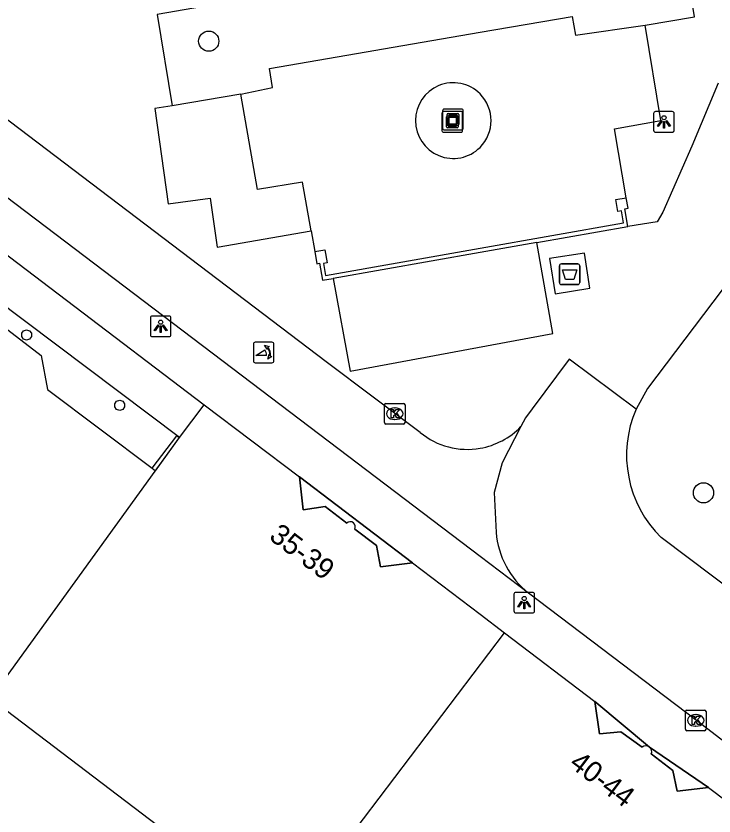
# Model space of a CAD drawing. Extents: x 161882 to 162509, y 381687 to 382379.
# Drawn here: x 161977.53 to 162011.33, y 382252.2 to 382290.93 of the extents above; entities that cross this region are included whole.
import ezdxf

# ---------------------------------------------------------------- set-up
doc = ezdxf.new("R2010")
doc.units = 0
for name, color, linetype in [('IMGEO_Afval_apart_plaats', 7, 'Continuous'), ('IMGEO_Boom', 7, 'Continuous'), ('IMGEO_Fietspad_open', 7, 'Continuous'), ('IMGEO_Kolk', 7, 'Continuous'), ('IMGEO_Kunstobject', 7, 'Continuous'), ('IMGEO_Lichtpunt', 7, 'Continuous'), ('IMGEO_Muur', 7, 'Continuous'), ('IMGEO_Pand', 7, 'Continuous'), ('IMGEO_Pand_nummerreeks', 7, 'Continuous'), ('IMGEO_Pand_overbouw', 7, 'Continuous'), ('IMGEO_Parkeervlak_open', 7, 'Continuous'), ('IMGEO_Poller', 7, 'Continuous'), ('IMGEO_Rijbaan_lokaal_open', 7, 'Continuous'), ('IMGEO_Voetpad_open', 7, 'Continuous')]:
    doc.layers.add(name, color=color, linetype=linetype)

msp = doc.modelspace()

# ---------------------------------------------------------------- linework, layer by layer
at = {"layer": 'IMGEO_Afval_apart_plaats'}
for p, q in [((162003.941, 382278.932), (162004.731, 382278.932)), ((162004.731, 382278.932), (162003.941, 382278.932)), ((162003.841, 382278.032), (162003.841, 382278.832)), ((162003.841, 382278.832), (162003.841, 382278.032)), ((162004.831, 382278.832), (162004.831, 382278.032)), ((162004.831, 382278.032), (162004.831, 382278.832)), ((162004.731, 382277.932), (162003.941, 382277.932)), ((162003.941, 382277.932), (162004.731, 382277.932))]:
    msp.add_line(p, q, dxfattribs=at)
msp.add_lwpolyline([(162003.984, 382278.646), (162004.688, 382278.646), (162004.539, 382278.176), (162004.133, 382278.176), (162003.984, 382278.646)], dxfattribs=at)
for centre, start, end in [((162003.941, 382278.832), 90, 180), ((162003.941, 382278.832), 90, 180), ((162004.731, 382278.832), 0, 90), ((162004.731, 382278.832), 360, 90), ((162003.941, 382278.032), 180, 270), ((162003.941, 382278.032), 180, 270), ((162004.731, 382278.032), 270, 0), ((162004.731, 382278.032), 270, 0)]:
    msp.add_arc(centre, 0.1, start, end, dxfattribs=at)
at = {"layer": 'IMGEO_Boom'}
for centre in [(161986.861, 382289.713), (162010.82, 382267.85)]:
    msp.add_circle(centre, 0.489, dxfattribs=at)
at = {"layer": 'IMGEO_Fietspad_open'}
msp.add_lwpolyline([(162002.346, 382262.989), (162000, 382264.77), (161990.844, 382271.72), (161969.897, 382287.586)], dxfattribs=at)
at = {"layer": 'IMGEO_Kolk'}
for p, q in [((161995.369, 382271.252), (161995.369, 382272.104)), ((161995.444, 382272.178), (161996.296, 382272.178)), ((161995.857, 382271.958), (161995.882, 382271.958)), ((161996.37, 382272.104), (161996.37, 382271.252)), ((161996.296, 382271.178), (161995.444, 382271.178)), ((161995.88, 382271.398), (161995.855, 382271.398)), ((162009.945, 382256.408), (162009.945, 382257.26)), ((162010.02, 382257.334), (162010.872, 382257.334)), ((162010.946, 382257.26), (162010.946, 382256.408)), ((162010.433, 382257.114), (162010.458, 382257.114)), ((162010.456, 382256.554), (162010.431, 382256.554)), ((162010.872, 382256.334), (162010.02, 382256.334))]:
    msp.add_line(p, q, dxfattribs=at)
for points in [[(161995.369, 382271.252), (161995.369, 382272.104)], [(161995.444, 382272.178), (161996.296, 382272.178)], [(161996.37, 382272.104), (161996.37, 382271.252)], [(161995.69, 382271.878), (161995.813, 382271.878), (161995.813, 382271.727), (161995.943, 382271.878), (161996.107, 382271.878), (161995.961, 382271.727), (161996.114, 382271.478), (161995.962, 382271.478), (161995.877, 382271.642), (161995.813, 382271.575), (161995.813, 382271.478), (161995.69, 382271.478), (161995.69, 382271.878)], [(161996.296, 382271.178), (161995.444, 382271.178)], [(162009.945, 382256.408), (162009.945, 382257.26)], [(162010.02, 382257.334), (162010.872, 382257.334)], [(162010.946, 382257.26), (162010.946, 382256.408)], [(162010.266, 382257.034), (162010.389, 382257.034), (162010.389, 382256.883), (162010.519, 382257.034), (162010.683, 382257.034), (162010.537, 382256.883), (162010.69, 382256.634), (162010.538, 382256.634), (162010.453, 382256.798), (162010.389, 382256.731), (162010.389, 382256.634), (162010.266, 382256.634), (162010.266, 382257.034)], [(162010.872, 382256.334), (162010.02, 382256.334)]]:
    msp.add_lwpolyline(points, dxfattribs=at)
for centre, start, end in [((161995.446, 382272.102), 91.552, 178.448), ((161995.446, 382272.102), 91.552, 178.448), ((161996.294, 382272.102), 1.552, 88.448), ((161996.294, 382272.102), 1.552, 88.448), ((161995.446, 382271.254), 181.552, 268.448), ((161995.446, 382271.254), 181.552, 268.448), ((161996.294, 382271.254), 271.552, 358.448), ((161996.294, 382271.254), 271.552, 358.448), ((162010.022, 382257.258), 91.552, 178.448), ((162010.022, 382257.258), 91.552, 178.448), ((162010.87, 382257.258), 1.552, 88.448), ((162010.87, 382257.258), 1.552, 88.448), ((162010.022, 382256.41), 181.552, 268.448), ((162010.022, 382256.41), 181.552, 268.448), ((162010.87, 382256.41), 271.552, 358.448), ((162010.87, 382256.41), 271.552, 358.448)]:
    msp.add_arc(centre, 0.0765, start, end, dxfattribs=at)
for centre, major_axis, ratio, start_param, end_param in [((161995.856, 382271.678), (-0.387, 0.002), 0.722429, 4.712389, 7.853982), ((161995.881, 382271.678), (-0.39, 0.002), 0.717154, 1.570796, 4.712389), ((162010.432, 382256.834), (-0.387, 0.002), 0.722429, 4.712389, 7.853982), ((162010.457, 382256.834), (-0.39, 0.002), 0.717154, 1.570796, 4.712389)]:
    msp.add_ellipse(centre, major_axis=major_axis, ratio=ratio, start_param=start_param, end_param=end_param, dxfattribs=at)
at = {"layer": 'IMGEO_Kunstobject'}
for p, q in [((161998.186, 382286.339), (161998.186, 382285.498)), ((161998.186, 382286.339), (161998.186, 382285.498)), ((161999.072, 382286.304), (161998.231, 382286.304)), ((161999.072, 382286.304), (161998.231, 382286.304)), ((161999.102, 382286.423), (161998.261, 382286.423)), ((161999.102, 382286.423), (161998.261, 382286.423)), ((161999.156, 382285.388), (161999.156, 382286.229)), ((161999.156, 382285.388), (161999.156, 382286.229)), ((161999.186, 382285.507), (161999.186, 382286.348)), ((161999.186, 382285.507), (161999.186, 382286.348)), ((161998.156, 382286.22), (161998.156, 382285.379)), ((161998.156, 382286.22), (161998.156, 382285.379)), ((161998.37, 382285.568), (161998.37, 382286.042)), ((161998.4, 382285.687), (161998.4, 382286.161)), ((161998.42, 382286.092), (161998.894, 382286.092)), ((161998.45, 382286.211), (161998.924, 382286.211)), ((161998.45, 382285.992), (161998.45, 382285.618)), ((161998.844, 382286.012), (161998.47, 382286.012)), ((161998.48, 382286.111), (161998.48, 382285.737)), ((161998.874, 382286.131), (161998.5, 382286.131)), ((161998.864, 382285.618), (161998.864, 382285.992)), ((161998.894, 382285.737), (161998.894, 382286.111)), ((161998.944, 382286.042), (161998.944, 382285.568)), ((161998.974, 382286.161), (161998.974, 382285.687)), ((161998.894, 382285.518), (161998.42, 382285.518)), ((161998.924, 382285.637), (161998.45, 382285.637)), ((161998.47, 382285.598), (161998.844, 382285.598)), ((161998.5, 382285.717), (161998.874, 382285.717)), ((161998.24, 382285.304), (161999.081, 382285.304)), ((161998.24, 382285.304), (161999.081, 382285.304)), ((161998.27, 382285.423), (161999.111, 382285.423)), ((161998.27, 382285.423), (161999.111, 382285.423))]:
    msp.add_line(p, q, dxfattribs=at)
for centre, radius, start, end in [((161998.234, 382286.226), 0.0779, 92.4484, 184.2845), ((161998.234, 382286.226), 0.0779, 92.4484, 184.2845), ((161998.264, 382286.345), 0.0779, 92.4484, 184.2845), ((161998.264, 382286.345), 0.0779, 92.4484, 184.2845), ((161999.078, 382286.226), 0.0779, 2.4484, 94.2845), ((161999.078, 382286.226), 0.0779, 2.4484, 94.2845), ((161999.108, 382286.345), 0.0779, 2.4484, 94.2845), ((161999.108, 382286.345), 0.0779, 2.4484, 94.2845), ((161998.42, 382286.042), 0.05, 90, 180), ((161998.45, 382286.161), 0.05, 90, 180), ((161998.47, 382285.992), 0.02, 90, 180), ((161998.5, 382286.111), 0.02, 90, 180), ((161998.844, 382285.992), 0.02, 360, 90), ((161998.874, 382286.111), 0.02, 360, 90), ((161998.894, 382286.042), 0.05, 360, 90), ((161998.924, 382286.161), 0.05, 360, 90), ((161998.264, 382285.501), 0.0779, 182.4484, 274.2845), ((161998.264, 382285.501), 0.0779, 182.4484, 274.2845), ((161998.42, 382285.568), 0.05, 180, 270), ((161998.45, 382285.687), 0.05, 180, 270), ((161998.47, 382285.618), 0.02, 180, 270), ((161998.5, 382285.737), 0.02, 180, 270), ((161998.844, 382285.618), 0.02, 270, 0), ((161998.874, 382285.737), 0.02, 270, 0), ((161998.894, 382285.568), 0.05, 270, 0), ((161998.924, 382285.687), 0.05, 270, 0), ((161999.108, 382285.501), 0.0779, 272.4484, 4.2845), ((161999.108, 382285.501), 0.0779, 272.4484, 4.2845), ((161998.234, 382285.382), 0.0779, 182.4484, 274.2845), ((161998.234, 382285.382), 0.0779, 182.4484, 274.2845), ((161999.078, 382285.382), 0.0779, 272.4484, 4.2845), ((161999.078, 382285.382), 0.0779, 272.4484, 4.2845)]:
    msp.add_arc(centre, radius, start, end, dxfattribs=at)
at = {"layer": 'IMGEO_Lichtpunt'}
for p, q in [((162009.308, 382286.302), (162008.5, 382286.302)), ((162009.308, 382286.302), (162008.5, 382286.302)), ((162008.406, 382286.207), (162008.406, 382285.4)), ((162008.406, 382286.207), (162008.406, 382285.4)), ((162009.402, 382285.4), (162009.402, 382286.207)), ((162009.402, 382285.4), (162009.402, 382286.207)), ((162008.5, 382285.306), (162009.308, 382285.306)), ((162008.5, 382285.306), (162009.308, 382285.306)), ((161984.034, 382276.311), (161984.034, 382275.504)), ((161984.034, 382276.311), (161984.034, 382275.504)), ((161984.936, 382276.406), (161984.128, 382276.406)), ((161984.936, 382276.406), (161984.128, 382276.406)), ((161985.03, 382275.504), (161985.03, 382276.311)), ((161985.03, 382275.504), (161985.03, 382276.311)), ((161984.128, 382275.41), (161984.936, 382275.41)), ((161984.128, 382275.41), (161984.936, 382275.41)), ((162002.541, 382263.031), (162001.733, 382263.031)), ((162002.541, 382263.031), (162001.733, 382263.031)), ((162001.639, 382262.936), (162001.639, 382262.129)), ((162001.639, 382262.936), (162001.639, 382262.129)), ((162002.635, 382262.129), (162002.635, 382262.936)), ((162002.635, 382262.129), (162002.635, 382262.936)), ((162001.733, 382262.035), (162002.541, 382262.035)), ((162001.733, 382262.035), (162002.541, 382262.035))]:
    msp.add_line(p, q, dxfattribs=at)
for points in [[(162008.78, 382285.871), (162008.819, 382285.843), (162008.631, 382285.581), (162008.593, 382285.608), (162008.78, 382285.871)], [(162008.992, 382285.843), (162009.03, 382285.87), (162009.217, 382285.608), (162009.178, 382285.58), (162008.992, 382285.843)], [(162008.882, 382285.823), (162008.929, 382285.823), (162008.929, 382285.501), (162008.882, 382285.501), (162008.882, 382285.823)], [(161984.408, 382275.975), (161984.447, 382275.947), (161984.259, 382275.685), (161984.221, 382275.712), (161984.408, 382275.975)], [(161984.51, 382275.927), (161984.557, 382275.927), (161984.557, 382275.605), (161984.51, 382275.605), (161984.51, 382275.927)], [(161984.62, 382275.947), (161984.658, 382275.974), (161984.845, 382275.712), (161984.806, 382275.684), (161984.62, 382275.947)], [(162002.013, 382262.6), (162002.052, 382262.572), (162001.864, 382262.31), (162001.826, 382262.337), (162002.013, 382262.6)], [(162002.115, 382262.552), (162002.162, 382262.552), (162002.162, 382262.23), (162002.115, 382262.23), (162002.115, 382262.552)], [(162002.225, 382262.572), (162002.263, 382262.599), (162002.45, 382262.337), (162002.411, 382262.309), (162002.225, 382262.572)]]:
    msp.add_lwpolyline(points, dxfattribs=at)
for centre in [(162008.905, 382286.005), (161984.533, 382276.109), (162002.138, 382262.734)]:
    msp.add_circle(centre, 0.0994, dxfattribs=at)
for centre, start, end in [((162008.5, 382286.207), 90, 180), ((162008.5, 382286.207), 90, 180), ((162009.308, 382286.207), 0, 90), ((162009.308, 382286.207), 0, 90), ((162008.5, 382285.4), 180, 270), ((162008.5, 382285.4), 180, 270), ((162009.308, 382285.4), 270, 0), ((162009.308, 382285.4), 270, 360), ((161984.128, 382276.311), 90, 180), ((161984.128, 382276.311), 90, 180), ((161984.936, 382276.311), 0, 90), ((161984.936, 382276.311), 0, 90), ((161984.128, 382275.504), 180, 270), ((161984.128, 382275.504), 180, 270), ((161984.936, 382275.504), 270, 0), ((161984.936, 382275.504), 270, 360), ((162001.733, 382262.936), 90, 180), ((162001.733, 382262.936), 90, 180), ((162002.541, 382262.936), 0, 90), ((162002.541, 382262.936), 0, 90), ((162001.733, 382262.129), 180, 270), ((162001.733, 382262.129), 180, 270), ((162002.541, 382262.129), 270, 0), ((162002.541, 382262.129), 270, 360)]:
    msp.add_arc(centre, 0.0946, start, end, dxfattribs=at)
at = {"layer": 'IMGEO_Muur'}
for points in [[(161991.995, 382279.528), (161992.478, 382279.613), (161992.59, 382278.982), (161992.414, 382278.951), (161992.517, 382278.369), (162000, 382279.69), (162006.947, 382280.916), (162006.845, 382281.494), (162006.673, 382281.464), (162006.57, 382282.043), (162007.079, 382282.133)], [(162007.152, 382280.747), (162007.003, 382281.593), (162007.169, 382281.623), (162007.079, 382282.133)], [(162002.743, 382279.968), (162007.152, 382280.747)], [(162002.743, 382279.968), (162000, 382279.484), (161992.881, 382278.227)], [(161991.995, 382279.528), (161992.099, 382278.936), (161992.227, 382278.959), (161992.372, 382278.137), (161992.881, 382278.227)]]:
    msp.add_lwpolyline(points, dxfattribs=at)
at = {"layer": 'IMGEO_Pand'}
for points in [[(161965.332, 382282.123), (161967.512, 382281.59), (161975.292, 382275.656), (161976.922, 382275.895), (161978.749, 382274.496), (161979.047, 382272.85), (161984.121, 382269.036), (161985.32, 382270.611), (161985.45, 382270.523)], [(161977.895, 382275.292), (161977.804, 382275.417), (161977.804, 382275.571), (161977.895, 382275.696), (161978.042, 382275.744), (161978.189, 382275.696), (161978.28, 382275.571), (161978.28, 382275.417), (161978.189, 382275.292), (161978.042, 382275.244), (161977.895, 382275.292)], [(161982.401, 382271.882), (161982.31, 382272.007), (161982.31, 382272.161), (161982.401, 382272.286), (161982.548, 382272.334), (161982.695, 382272.286), (161982.786, 382272.161), (161982.786, 382272.007), (161982.695, 382271.882), (161982.548, 382271.834), (161982.401, 382271.882)], [(161985.45, 382270.523), (161986.642, 382272.1)], [(161986.642, 382272.1), (161991.25, 382268.628)], [(161976.285, 382257.889), (161985.45, 382270.523)], [(161993.545, 382266.378), (161992.504, 382267.191), (161991.441, 382267.021), (161991.25, 382268.628)], [(161996.729, 382264.459), (161995.18, 382264.27), (161994.978, 382265.301), (161993.928, 382266.088)], [(161996.729, 382264.459), (162000, 382261.97), (162001.181, 382261.071)], [(161990.561, 382247.065), (162001.181, 382261.071)], [(162001.181, 382261.071), (162005.558, 382257.74)], [(161976.285, 382257.889), (161986.69, 382250), (161990.561, 382247.065)], [(162007.852, 382255.531), (162006.821, 382256.276), (162005.779, 382256.186), (162005.558, 382257.74)], [(162011.059, 382253.58), (162009.537, 382253.409), (162009.335, 382254.407), (162008.293, 382255.208)], [(162011.059, 382253.58), (162015.722, 382250.073)]]:
    msp.add_lwpolyline(points, dxfattribs=at)
for centre, radius, start, end in [((161993.717, 382266.207), 0.242, 330.6785, 135.057), ((162008.034, 382255.325), 0.275, 51.4068, 131.5059), ((162008.039, 382255.319), 0.277, 336.4836, 52.8845)]:
    msp.add_arc(centre, radius, start, end, dxfattribs=at)
at = {"layer": 'IMGEO_Pand_overbouw'}
msp.add_lwpolyline([(161966.04, 382285.113), (161965.332, 382282.123), (161967.512, 382281.59), (161975.292, 382275.656), (161976.922, 382275.895), (161978.749, 382274.496), (161979.047, 382272.85), (161984.121, 382269.036), (161984.283, 382268.914), (161985.45, 382270.523)], close=True, dxfattribs=at)
for points in [[(161996.729, 382264.459), (161991.25, 382268.628), (161991.441, 382267.021), (161992.504, 382267.191), (161993.545, 382266.378)], [(161993.928, 382266.088), (161994.978, 382265.301), (161995.18, 382264.27), (161996.729, 382264.459)], [(162008.206, 382255.54), (162005.558, 382257.74), (162005.779, 382256.186), (162006.821, 382256.276), (162007.852, 382255.531)], [(162011.059, 382253.58), (162008.206, 382255.54)], [(162008.293, 382255.208), (162009.335, 382254.407), (162009.537, 382253.409), (162011.059, 382253.58)]]:
    msp.add_lwpolyline(points, dxfattribs=at)
for centre, radius, start, end in [((161993.717, 382266.207), 0.242, 330.6785, 135.057), ((162008.034, 382255.325), 0.275, 51.4068, 131.5059), ((162008.039, 382255.319), 0.277, 336.4836, 52.8845)]:
    msp.add_arc(centre, radius, start, end, dxfattribs=at)
at = {"layer": 'IMGEO_Parkeervlak_open'}
for points in [[(162007.991, 382290.487), (162010.389, 382290.894), (162009.655, 382295.317)], [(161988.423, 382287.15), (161985.082, 382286.588)]]:
    msp.add_lwpolyline(points, dxfattribs=at)
at = {"layer": 'IMGEO_Poller'}
for p, q in [((161989.021, 382275.044), (161989.021, 382274.237)), ((161989.021, 382275.044), (161989.021, 382274.237)), ((161989.923, 382275.139), (161989.115, 382275.139)), ((161989.923, 382275.139), (161989.115, 382275.139)), ((161990.017, 382274.237), (161990.017, 382275.044)), ((161990.017, 382274.237), (161990.017, 382275.044)), ((161989.115, 382274.142), (161989.923, 382274.142)), ((161989.115, 382274.142), (161989.923, 382274.142))]:
    msp.add_line(p, q, dxfattribs=at)
for points in [[(161989.7, 382274.868), (161989.688, 382274.795), (161989.563, 382275)], [(161989.563, 382275), (161989.794, 382274.934), (161989.723, 382274.902)], [(161989.656, 382274.495), (161989.143, 382274.495), (161989.573, 382274.77)], [(161989.716, 382274.323), (161989.782, 382274.554), (161989.812, 382274.486)], [(161989.848, 382274.459), (161989.92, 382274.448), (161989.716, 382274.323)]]:
    msp.add_lwpolyline(points, dxfattribs=at)
for centre, radius, start, end in [((161989.115, 382275.044), 0.0946, 90, 180), ((161989.115, 382275.044), 0.0946, 90, 180), ((161989.923, 382275.044), 0.0946, 0, 90), ((161989.923, 382275.044), 0.0946, 0, 90), ((161989.328, 382274.545), 0.332, 351.3247, 42.4854), ((161989.342, 382274.555), 0.476, 351.7527, 41.1691), ((161989.342, 382274.555), 0.516, 349.3569, 42.2912), ((161989.115, 382274.237), 0.0946, 180, 270), ((161989.115, 382274.237), 0.0946, 180, 270), ((161989.923, 382274.237), 0.0946, 270, 0), ((161989.923, 382274.237), 0.0946, 270, 0)]:
    msp.add_arc(centre, radius, start, end, dxfattribs=at)
at = {"layer": 'IMGEO_Rijbaan_lokaal_open'}
for points in [[(162009.655, 382295.317), (162006.144, 382294.743), (162006.01, 382295.418), (162000, 382294.392), (161987.321, 382292.228), (161987.441, 382291.529), (161984.356, 382291.003), (161985.082, 382286.588)], [(161997.102, 382270.769), (161992.553, 382274.195), (161971.544, 382290.116)], [(162011.538, 382287.672), (162010.261, 382284.624), (162008.856, 382281.427), (162008.577, 382280.965), (162007.152, 382280.747)], [(161985.082, 382286.588), (161984.251, 382286.448), (161984.897, 382281.835), (161986.936, 382282.12), (161987.268, 382279.744), (161991.819, 382280.538)], [(161991.819, 382280.538), (161991.995, 382279.528)], [(161992.881, 382278.227), (161993.717, 382273.732), (162003.522, 382275.555), (162002.743, 382279.968)], [(162005.051, 382279.455), (162003.364, 382279.187), (162003.635, 382277.48), (162005.322, 382277.748), (162005.051, 382279.455)], [(162011.721, 382277.668), (162008.112, 382272.899), (162007.553, 382271.9)], [(162007.553, 382271.9), (162004.319, 382274.316), (162002.523, 382271.914), (162002.203, 382271.473), (162001.978, 382271.055)], [(162001.978, 382271.055), (162001.065, 382269.306), (162000.685, 382267.858), (162000.774, 382265.936)], [(162023.872, 382254.304), (162008.77, 382265.681)], [(162018.527, 382250.66), (162010.479, 382256.829), (162002.346, 382262.989)]]:
    msp.add_lwpolyline(points, dxfattribs=at)
for centre, radius, start, end in [((162012.692, 382269.677), 5.599, 156.6083, 225.5363), ((161999.379, 382273.529), 3.578, 230.4721, 279.9902), ((161999.367, 382273.585), 3.636, 280.0249, 315.8974), ((162005.026, 382266.311), 4.269, 185.046, 231.1071)]:
    msp.add_arc(centre, radius, start, end, dxfattribs=at)
at = {"layer": 'IMGEO_Voetpad_open'}
for points in [[(161988.423, 382287.15), (161989.946, 382287.471), (161989.8, 382288.386), (162000, 382290.142), (162004.463, 382290.911), (162004.614, 382290.004), (162007.991, 382290.487)], [(162007.079, 382282.133), (162006.502, 382285.471), (162008.751, 382285.879), (162007.991, 382290.487)], [(161941.807, 382283.041), (161966.622, 382287.308), (161986.642, 382272.1)], [(161991.819, 382280.538), (161991.408, 382282.893), (161989.218, 382282.537), (161988.423, 382287.15)], [(161991.25, 382268.628), (161996.729, 382264.459)], [(162005.558, 382257.74), (162008.206, 382255.54)], [(162008.206, 382255.54), (162011.059, 382253.58)]]:
    msp.add_lwpolyline(points, dxfattribs=at)
for centre, radius, start, end in [((161998.703, 382285.866), 1.832, 44.9351, 315.0649), ((161998.696, 382285.866), 1.837, 315.2264, 44.7736)]:
    msp.add_arc(centre, radius, start, end, dxfattribs=at)

# ---------------------------------------------------------------- texts
at = {"layer": 'IMGEO_Pand_nummerreeks'}
for s, rotation, p in [('35-39', 322.8691, (161989.731, 382265.638)), ('40-44', 323.0518, (162004.265, 382254.628))]:
    msp.add_text(s, height=1, rotation=rotation, dxfattribs=at).set_placement(p)

doc.saveas('drawing.dxf')
